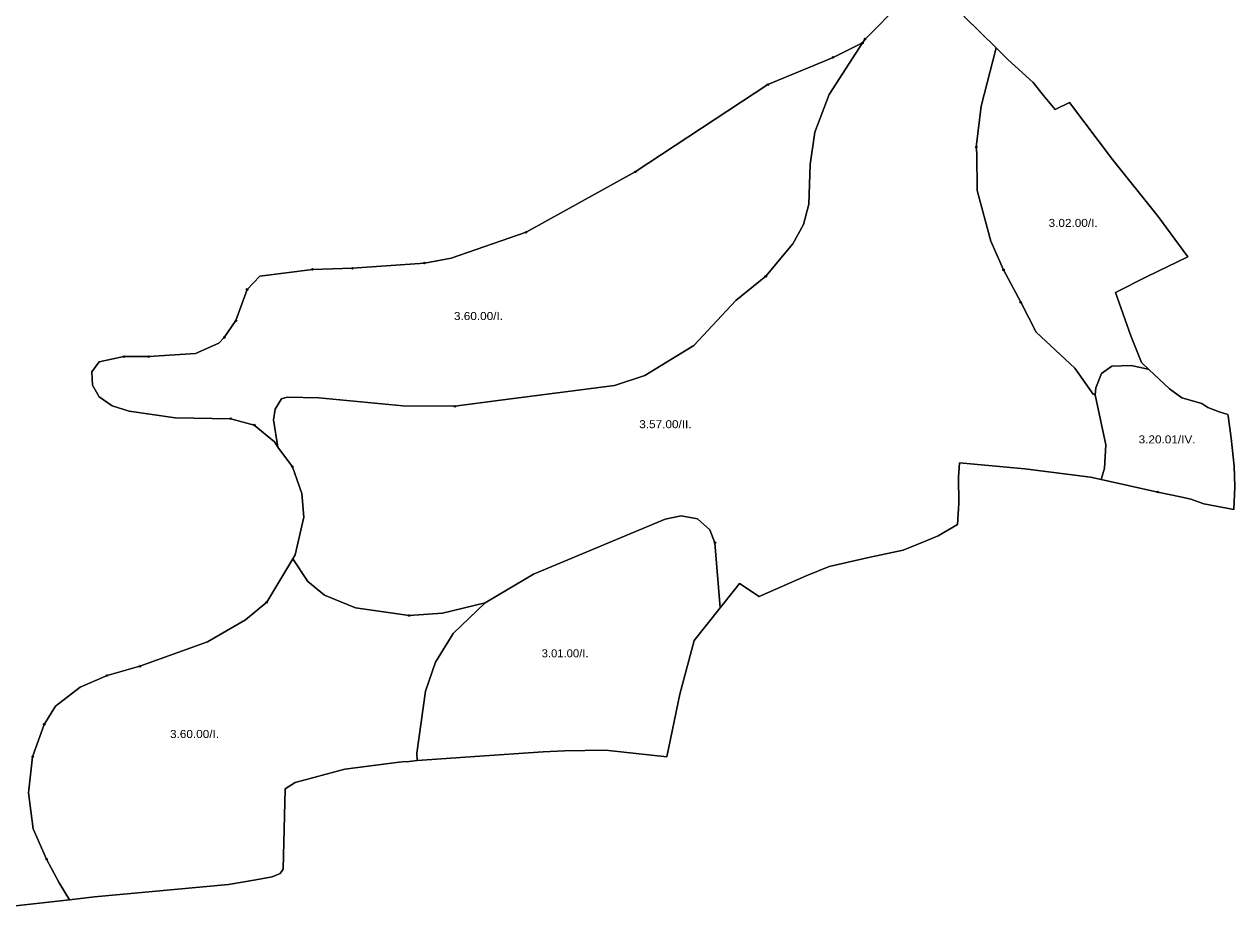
# Model space of a CAD drawing. Extents: x -650455 to -642254, y -1075222 to -1066610.
# Drawn here: x -643766 to -642254, y -1070756 to -1069652 of the extents above; entities that cross this region are included whole.
import ezdxf
from ezdxf.enums import TextEntityAlignment as Align

# ---------------------------------------------------------------- set-up
doc = ezdxf.new("R2010")
doc.units = 0
doc.header["$LTSCALE"] = 4
doc.header["$PDMODE"] = 32
doc.header["$PDSIZE"] = 2
for name, color, linetype, lineweight in [('1', 7, 'Continuous', 25), ('11', 7, 'Continuous', 13), ('12', 7, 'Continuous', 13), ('14', 7, 'Continuous', 13)]:
    doc.layers.add(name, color=color, linetype=linetype, lineweight=lineweight)
doc.layers.add('2', color=7, linetype='Continuous')

msp = doc.modelspace()

# ---------------------------------------------------------------- linework, layer by layer
at = {"layer": '1'}
for points in [[(-642670.5, -1069625.501), (-642716, -1069671), (-642719.154, -1069675.872), (-642756, -1069694.001), (-642837.5, -1069728), (-643003, -1069837), (-643139.5, -1069912.501), (-643233, -1069945.001), (-643266.5, -1069951), (-643356.5, -1069957.501), (-643406.5, -1069959), (-643472, -1069967.5), (-643488, -1069984), (-643502, -1070023.001), (-643516.5, -1070044), (-643523.5, -1070051.001), (-643552.5, -1070064), (-643611, -1070068), (-643642, -1070068), (-643673, -1070074.501), (-643682, -1070087.001), (-643681, -1070103.501), (-643673, -1070118), (-643656.5, -1070129.5), (-643635.5, -1070136.001), (-643578, -1070144.501), (-643508.5, -1070145.5), (-643479, -1070153.5), (-643454, -1070174.5), (-643449.5, -1070181.001), (-643431.5, -1070205.5), (-643419.5, -1070239), (-643417, -1070268.501), (-643428, -1070315.5), (-643431, -1070320.5), (-643463.5, -1070375.001), (-643490, -1070397), (-643537.5, -1070424.5)], [(-643244, -1070388.5), (-643285.5, -1070391.501), (-643352.5, -1070382.001), (-643391.5, -1070366.001), (-643412, -1070349), (-643431, -1070320.5), (-643428, -1070315.5), (-643417, -1070268.501), (-643419.5, -1070239), (-643431.5, -1070205.5), (-643449.5, -1070181.001), (-643455, -1070147.001), (-643453, -1070133.5), (-643445, -1070120.5), (-643438, -1070118.501), (-643398.5, -1070119.501), (-643293.5, -1070129.5), (-643228.5, -1070130), (-643171.5, -1070122.501), (-643029, -1070104.001), (-642991, -1070091.501), (-642930, -1070054.001), (-642877.5, -1069998.001), (-642840, -1069967.5), (-642806, -1069927), (-642793, -1069903), (-642786, -1069877.5), (-642784.5, -1069828.001), (-642778.5, -1069787.501), (-642761, -1069740.5), (-642719.154, -1069675.872), (-642716, -1069671), (-642670.5, -1069625.501)], [(-642592.226, -1069642.762), (-642552.355, -1069682.197)], [(-643449.5, -1070181.001), (-643454, -1070174.5), (-643479, -1070153.5), (-643508.5, -1070145.5), (-643578, -1070144.501), (-643635.5, -1070136.001), (-643656.5, -1070129.5), (-643673, -1070118), (-643681, -1070103.501), (-643682, -1070087.001), (-643673, -1070074.501), (-643642, -1070068), (-643611, -1070068), (-643552.5, -1070064), (-643523.5, -1070051.001), (-643516.5, -1070044), (-643502, -1070023.001), (-643488, -1069984), (-643472, -1069967.5), (-643406.5, -1069959), (-643356.5, -1069957.501), (-643266.5, -1069951), (-643233, -1069945.001), (-643139.5, -1069912.501), (-643003, -1069837), (-642837.5, -1069728), (-642756, -1069694.001), (-642719.154, -1069675.872), (-642761, -1069740.5), (-642778.5, -1069787.501), (-642784.5, -1069828.001), (-642786, -1069877.5), (-642793, -1069903), (-642806, -1069927), (-642840, -1069967.5), (-642877.5, -1069998.001), (-642930, -1070054.001), (-642991, -1070091.501), (-643029, -1070104.001), (-643171.5, -1070122.501)], [(-642552.355, -1069682.197), (-642571, -1069755.001), (-642577, -1069806), (-642576.5, -1069813.5), (-642576, -1069860.501), (-642559, -1069923.5), (-642543, -1069959.5), (-642521.5, -1070000), (-642502, -1070037.501), (-642454, -1070082.501), (-642431, -1070115.001), (-642428.5, -1070115.501), (-642415, -1070178), (-642417, -1070207.501), (-642420.956, -1070221.525), (-642434.435, -1070218.539), (-642516.398, -1070207.98), (-642598.051, -1070200.836), (-642599.293, -1070218.539), (-642598.672, -1070251.463), (-642600.535, -1070277.863), (-642624.441, -1070291.84), (-642639.802, -1070298.162), (-642668.217, -1070309.854), (-642709.509, -1070318.552), (-642760.737, -1070330.354), (-642789.61, -1070341.846), (-642848.288, -1070367.626), (-642872.815, -1070351.474), (-642878.961, -1070359.21), (-642896.975, -1070381.886), (-642903.5, -1070300.5), (-642910, -1070284.501), (-642925.5, -1070270.5), (-642945.5, -1070267), (-642965.5, -1070271), (-643130, -1070340), (-643186.433, -1070373.114), (-643190.5, -1070375.5), (-643244, -1070388.5)], [(-643171.5, -1070122.501), (-643228.5, -1070130), (-643293.5, -1070129.5), (-643398.5, -1070119.501), (-643438, -1070118.501), (-643445, -1070120.5), (-643453, -1070133.5), (-643455, -1070147.001), (-643449.5, -1070181.001)], [(-643537.5, -1070424.5), (-643622, -1070455.001), (-643663, -1070466.5), (-643696.5, -1070481), (-643727.5, -1070505), (-643741.5, -1070527.501), (-643756, -1070568.001), (-643761, -1070613.001), (-643755.5, -1070658.001), (-643738.5, -1070696), (-643723, -1070725.5), (-643709.901, -1070746.632), (-643788.642, -1070755.533)]]:
    msp.add_lwpolyline(points, dxfattribs=at)
for points in [[(-642361.321, -1070084.08), (-642364.5, -1070083.001), (-642383.5, -1070079.001), (-642407.5, -1070080), (-642420.5, -1070089), (-642427.5, -1070107.001), (-642428.5, -1070115.501), (-642431, -1070115.001), (-642454, -1070082.501), (-642502, -1070037.501), (-642521.5, -1070000), (-642543, -1069959.5), (-642559, -1069923.5), (-642576, -1069860.501), (-642576.5, -1069813.5), (-642577, -1069806), (-642571, -1069755.001), (-642552.355, -1069682.197), (-642537.584, -1069696.806), (-642505.916, -1069725.382), (-642492.836, -1069741.408), (-642478.285, -1069759.236), (-642460.588, -1069750.229), (-642406.877, -1069821.665), (-642349.751, -1069892.791), (-642312.805, -1069943.419), (-642363.412, -1069967.956), (-642403.152, -1069987.834), (-642383.903, -1070041.878), (-642370.553, -1070075.422)], [(-642361.321, -1070084.08), (-642335.781, -1070108.035), (-642320.258, -1070119.527), (-642295.202, -1070126.517), (-642287.754, -1070131.386), (-642273.43, -1070137.117), (-642262.687, -1070140.46), (-642262.467, -1070141.96), (-642258.374, -1070169.876), (-642254.86, -1070204.888), (-642254.016, -1070230.758), (-642255.33, -1070259.177), (-642292.811, -1070251.773), (-642309.077, -1070246.214), (-642321.735, -1070243.076), (-642350.298, -1070237.176), (-642420.956, -1070221.525), (-642417, -1070207.501), (-642415, -1070178), (-642428.5, -1070115.501), (-642427.5, -1070107.001), (-642420.5, -1070089), (-642407.5, -1070080), (-642383.5, -1070079.001), (-642364.5, -1070083.001)], [(-642896.975, -1070381.886), (-642929.32, -1070422.6), (-642947.327, -1070490), (-642963.471, -1070567.958), (-643040.151, -1070559.763), (-643091.317, -1070560.773), (-643118.269, -1070562.07), (-643203.593, -1070567.547), (-643269.316, -1070572.302), (-643275.344, -1070572.875), (-643276, -1070563.5), (-643265, -1070486), (-643252.5, -1070450), (-643230.5, -1070414.001), (-643190.5, -1070375.5), (-643186.433, -1070373.114), (-643130, -1070340), (-642965.5, -1070271), (-642945.5, -1070267), (-642925.5, -1070270.5), (-642910, -1070284.501), (-642903.5, -1070300.5)], [(-643190.5, -1070375.5), (-643230.5, -1070414.001), (-643252.5, -1070450), (-643265, -1070486), (-643276, -1070563.5), (-643275.344, -1070572.875), (-643289.061, -1070574.177), (-643290.031, -1070573.836), (-643298.218, -1070574.877), (-643365.785, -1070583.463), (-643427.878, -1070600.237), (-643440.607, -1070608.311), (-643443.091, -1070708.324), (-643446.816, -1070713.915), (-643456.751, -1070718.263), (-643476.945, -1070721.725), (-643511.083, -1070727.58), (-643678.736, -1070743.109), (-643709.901, -1070746.632), (-643723, -1070725.5), (-643738.5, -1070696), (-643755.5, -1070658.001), (-643761, -1070613.001), (-643756, -1070568.001), (-643741.5, -1070527.501), (-643727.5, -1070505), (-643696.5, -1070481), (-643663, -1070466.5), (-643622, -1070455.001), (-643537.5, -1070424.5), (-643490, -1070397), (-643463.5, -1070375.001), (-643431, -1070320.5), (-643412, -1070349), (-643391.5, -1070366.001), (-643352.5, -1070382.001), (-643285.5, -1070391.501), (-643244, -1070388.5)]]:
    msp.add_lwpolyline(points, close=True, dxfattribs=at)
at = {"layer": '11'}
for p, q in [((-642756, -1069694.001), (-642719.154, -1069675.872)), ((-643139.5, -1069912.501), (-643003, -1069837)), ((-643406.5, -1069959), (-643356.5, -1069957.501)), ((-642543, -1069959.5), (-642521.5, -1070000)), ((-643502, -1070023.001), (-643516.5, -1070044)), ((-643741.5, -1070527.501), (-643756, -1070568.001))]:
    msp.add_line(p, q, dxfattribs=at)
for points in [[(-642719.154, -1069675.872), (-642716, -1069671), (-642670.5, -1069625.501)], [(-642840, -1069967.5), (-642806, -1069927), (-642793, -1069903), (-642786, -1069877.5), (-642784.5, -1069828.001), (-642778.5, -1069787.501), (-642761, -1069740.5), (-642719.154, -1069675.872), (-642756, -1069694.001), (-642837.5, -1069728)], [(-642521.5, -1070000), (-642502, -1070037.501), (-642454, -1070082.501), (-642431, -1070115.001), (-642428.5, -1070115.501), (-642427.5, -1070107.001), (-642420.5, -1070089), (-642407.5, -1070080), (-642383.5, -1070079.001), (-642364.5, -1070083.001), (-642361.321, -1070084.08), (-642370.553, -1070075.422), (-642383.903, -1070041.878), (-642403.152, -1069987.834), (-642363.412, -1069967.956), (-642312.805, -1069943.419), (-642349.751, -1069892.791), (-642406.877, -1069821.665), (-642460.588, -1069750.229), (-642478.285, -1069759.236), (-642492.836, -1069741.408), (-642505.916, -1069725.382), (-642537.584, -1069696.806), (-642552.355, -1069682.197), (-642571, -1069755.001), (-642577, -1069806), (-642576.5, -1069813.5), (-642576, -1069860.501)], [(-643003, -1069837), (-642837.5, -1069728), (-642756, -1069694.001)], [(-642837.5, -1069728), (-643003, -1069837), (-643139.5, -1069912.501), (-643233, -1069945.001), (-643266.5, -1069951)], [(-642576, -1069860.501), (-642559, -1069923.5), (-642543, -1069959.5)], [(-643356.5, -1069957.501), (-643266.5, -1069951), (-643233, -1069945.001), (-643139.5, -1069912.501)], [(-643266.5, -1069951), (-643356.5, -1069957.501), (-643406.5, -1069959), (-643472, -1069967.5), (-643488, -1069984), (-643502, -1070023.001)], [(-643488, -1069984), (-643472, -1069967.5), (-643406.5, -1069959)], [(-643228.5, -1070130), (-643171.5, -1070122.501), (-643029, -1070104.001), (-642991, -1070091.501), (-642930, -1070054.001), (-642877.5, -1069998.001), (-642840, -1069967.5)], [(-643611, -1070068), (-643552.5, -1070064), (-643523.5, -1070051.001), (-643516.5, -1070044), (-643502, -1070023.001), (-643488, -1069984)], [(-643516.5, -1070044), (-643523.5, -1070051.001), (-643552.5, -1070064), (-643611, -1070068), (-643642, -1070068)], [(-643508.5, -1070145.5), (-643578, -1070144.501), (-643635.5, -1070136.001), (-643656.5, -1070129.5), (-643673, -1070118), (-643681, -1070103.501), (-643682, -1070087.001), (-643673, -1070074.501), (-643642, -1070068), (-643611, -1070068)], [(-643642, -1070068), (-643673, -1070074.501), (-643682, -1070087.001), (-643681, -1070103.501), (-643673, -1070118), (-643656.5, -1070129.5), (-643635.5, -1070136.001), (-643578, -1070144.501), (-643508.5, -1070145.5), (-643479, -1070153.5)], [(-643479, -1070153.5), (-643454, -1070174.5), (-643449.5, -1070181.001), (-643455, -1070147.001), (-643453, -1070133.5), (-643445, -1070120.5), (-643438, -1070118.501), (-643398.5, -1070119.501), (-643293.5, -1070129.5), (-643228.5, -1070130)], [(-643622, -1070455.001), (-643537.5, -1070424.5), (-643490, -1070397), (-643463.5, -1070375.001), (-643431, -1070320.5), (-643428, -1070315.5), (-643417, -1070268.501), (-643419.5, -1070239), (-643431.5, -1070205.5), (-643449.5, -1070181.001), (-643454, -1070174.5), (-643479, -1070153.5), (-643508.5, -1070145.5)], [(-642903.5, -1070300.5), (-642910, -1070284.501), (-642925.5, -1070270.5), (-642945.5, -1070267), (-642965.5, -1070271), (-643130, -1070340), (-643186.433, -1070373.114), (-643190.5, -1070375.5), (-643230.5, -1070414.001), (-643252.5, -1070450), (-643265, -1070486), (-643276, -1070563.5)], [(-643276, -1070563.5), (-643275.344, -1070572.875), (-643269.316, -1070572.302), (-643203.593, -1070567.547), (-643118.269, -1070562.07), (-643091.317, -1070560.773), (-643040.151, -1070559.763), (-642963.471, -1070567.958), (-642947.327, -1070490), (-642929.32, -1070422.6), (-642896.975, -1070381.886), (-642903.5, -1070300.5)], [(-643738.5, -1070696), (-643723, -1070725.5), (-643709.901, -1070746.632), (-643678.736, -1070743.109), (-643511.083, -1070727.58), (-643476.945, -1070721.725), (-643456.751, -1070718.263), (-643446.816, -1070713.915), (-643443.091, -1070708.324), (-643440.607, -1070608.311), (-643427.878, -1070600.237), (-643365.785, -1070583.463), (-643298.218, -1070574.877), (-643290.031, -1070573.836), (-643289.061, -1070574.177), (-643275.344, -1070572.875), (-643276, -1070563.5), (-643265, -1070486), (-643252.5, -1070450), (-643230.5, -1070414.001), (-643190.5, -1070375.5), (-643244, -1070388.5), (-643285.5, -1070391.501), (-643352.5, -1070382.001), (-643391.5, -1070366.001), (-643412, -1070349), (-643431, -1070320.5), (-643463.5, -1070375.001)], [(-643463.5, -1070375.001), (-643490, -1070397), (-643537.5, -1070424.5), (-643622, -1070455.001), (-643663, -1070466.5)], [(-643788.642, -1070755.533), (-643709.901, -1070746.632), (-643723, -1070725.5), (-643738.5, -1070696), (-643755.5, -1070658.001), (-643761, -1070613.001), (-643756, -1070568.001), (-643741.5, -1070527.501), (-643727.5, -1070505), (-643696.5, -1070481), (-643663, -1070466.5), (-643622, -1070455.001)], [(-643663, -1070466.5), (-643696.5, -1070481), (-643727.5, -1070505), (-643741.5, -1070527.501)], [(-643756, -1070568.001), (-643761, -1070613.001), (-643755.5, -1070658.001), (-643738.5, -1070696)]]:
    msp.add_lwpolyline(points, dxfattribs=at)
for p in [(-642719.154, -1069675.872), (-642756, -1069694.001), (-642837.5, -1069728), (-643003, -1069837), (-643139.5, -1069912.501), (-643406.5, -1069959), (-643356.5, -1069957.501), (-643266.5, -1069951), (-642543, -1069959.5), (-642840, -1069967.5), (-643488, -1069984), (-642521.5, -1070000), (-643502, -1070023.001), (-643516.5, -1070044), (-643642, -1070068), (-643611, -1070068), (-643228.5, -1070130), (-643508.5, -1070145.5), (-643479, -1070153.5), (-642903.5, -1070300.5), (-643463.5, -1070375.001), (-643622, -1070455.001), (-643663, -1070466.5), (-643741.5, -1070527.501), (-643756, -1070568.001), (-643738.5, -1070696)]:
    msp.add_point(p, dxfattribs=at)
at = {"layer": '12'}
for points in [[(-642577, -1069806), (-642571, -1069755.001), (-642552.355, -1069682.197), (-642592.226, -1069642.762), (-642581.981, -1069623.817), (-642572.046, -1069609.218), (-642599.044, -1069579.399), (-642617.261, -1069559.279), (-642619.5, -1069561.501), (-642670.5, -1069625.501), (-642716, -1069671)], [(-642716, -1069671), (-642719.154, -1069675.872), (-642761, -1069740.5), (-642778.5, -1069787.501), (-642784.5, -1069828.001), (-642786, -1069877.5), (-642793, -1069903), (-642806, -1069927), (-642840, -1069967.5), (-642877.5, -1069998.001), (-642930, -1070054.001), (-642991, -1070091.501), (-643029, -1070104.001), (-643171.5, -1070122.501), (-643228.5, -1070130), (-643293.5, -1070129.5), (-643398.5, -1070119.501), (-643438, -1070118.501), (-643445, -1070120.5), (-643453, -1070133.5), (-643455, -1070147.001), (-643449.5, -1070181.001), (-643431.5, -1070205.5)], [(-643285.5, -1070391.501), (-643244, -1070388.5), (-643190.5, -1070375.5), (-643186.433, -1070373.114), (-643130, -1070340), (-642965.5, -1070271), (-642945.5, -1070267), (-642925.5, -1070270.5), (-642910, -1070284.501), (-642903.5, -1070300.5), (-642896.975, -1070381.886), (-642878.961, -1070359.21), (-642872.815, -1070351.474), (-642848.288, -1070367.626), (-642789.61, -1070341.846), (-642760.737, -1070330.354), (-642709.509, -1070318.552), (-642668.217, -1070309.854), (-642639.802, -1070298.162), (-642624.441, -1070291.84), (-642600.535, -1070277.863), (-642598.672, -1070251.463), (-642599.293, -1070218.539), (-642598.051, -1070200.836), (-642516.398, -1070207.98), (-642434.435, -1070218.539), (-642420.956, -1070221.525), (-642417, -1070207.501), (-642415, -1070178), (-642428.5, -1070115.501), (-642431, -1070115.001), (-642454, -1070082.501), (-642502, -1070037.501), (-642521.5, -1070000), (-642543, -1069959.5), (-642559, -1069923.5), (-642576, -1069860.501), (-642576.5, -1069813.5), (-642577, -1069806)], [(-643431.5, -1070205.5), (-643419.5, -1070239), (-643417, -1070268.501), (-643428, -1070315.5), (-643431, -1070320.5), (-643412, -1070349), (-643391.5, -1070366.001), (-643352.5, -1070382.001), (-643285.5, -1070391.501)]]:
    msp.add_lwpolyline(points, dxfattribs=at)
for p in [(-642716, -1069671), (-642577, -1069806), (-643431.5, -1070205.5), (-643285.5, -1070391.501)]:
    msp.add_point(p, dxfattribs=at)
at = {"layer": '14'}
msp.add_lwpolyline([(-642350.298, -1070237.176), (-642321.735, -1070243.076), (-642309.077, -1070246.214), (-642292.811, -1070251.773), (-642255.33, -1070259.177), (-642254.016, -1070230.758), (-642254.86, -1070204.888), (-642258.374, -1070169.876), (-642262.467, -1070141.96), (-642262.687, -1070140.46), (-642273.43, -1070137.117), (-642287.754, -1070131.386), (-642295.202, -1070126.517), (-642320.258, -1070119.527), (-642335.781, -1070108.035), (-642361.321, -1070084.08), (-642364.5, -1070083.001), (-642383.5, -1070079.001), (-642407.5, -1070080), (-642420.5, -1070089), (-642427.5, -1070107.001), (-642428.5, -1070115.501), (-642415, -1070178), (-642417, -1070207.501), (-642420.956, -1070221.525)], close=True, dxfattribs=at)
msp.add_point((-642350.298, -1070237.176), dxfattribs=at)

# ---------------------------------------------------------------- texts
at = {"layer": '2'}
for s, width, p in [('3.02.00/I.', 1.1, (-642456.002, -1069905.833)), ('3.60.00/I.', 1.1, (-643198.943, -1070022.212)), ('3.57.00/II.', 1.1, (-642965.377, -1070157.389)), ('3.20.01/IV.', 1.1, (-642338.615, -1070176.387)), ('3.01.00/I.', 1.05, (-643090.713, -1070443.748)), ('3.60.00/I.', 1.1, (-643553.671, -1070544.564))]:
    msp.add_text(s, height=10, dxfattribs=dict(at, width=width)).set_placement(p, align=Align.CENTER)

doc.saveas('drawing.dxf')
